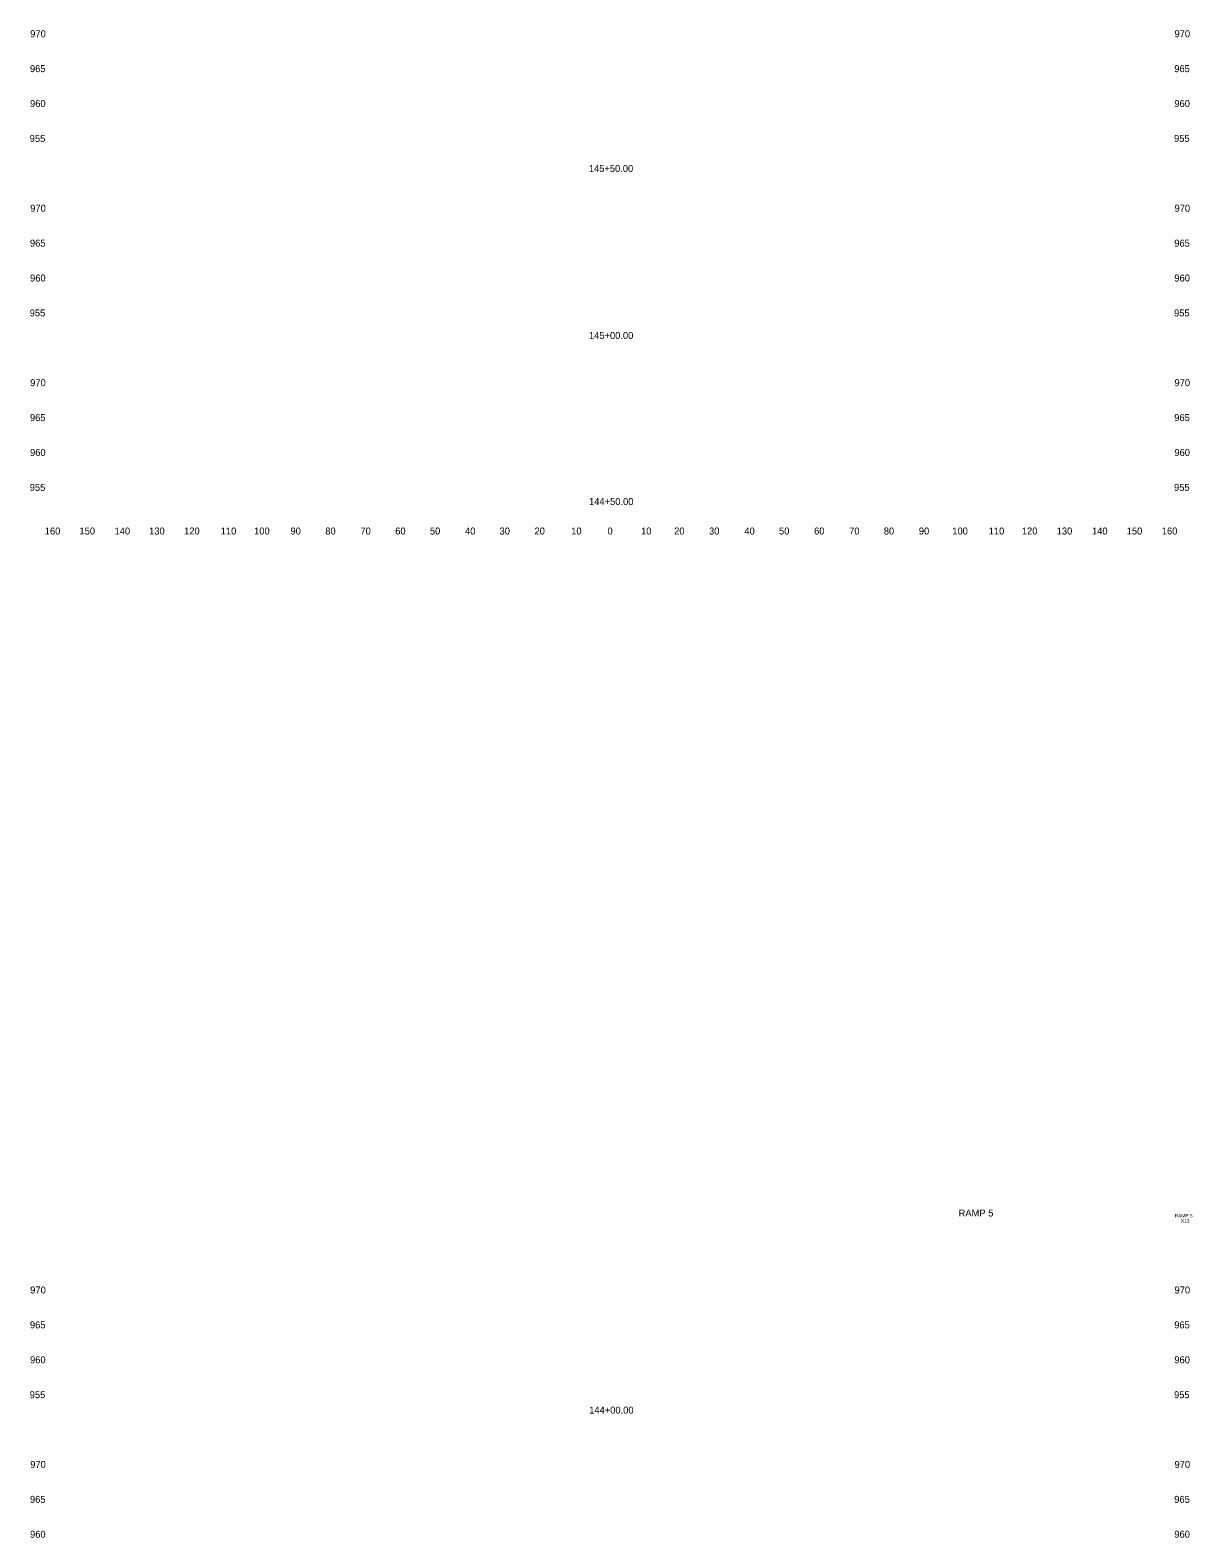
# Model space of a CAD drawing. Extents: x 4994 to 5842, y 4997 to 8804.
# Drawn here: x 5508.9 to 5841.7, y 5910 to 6342 of the extents above; entities that cross this region are included whole.
import ezdxf

# ---------------------------------------------------------------- set-up
doc = ezdxf.new("R2010")
doc.units = 0
for name, color, linetype in [('CLS_Search_Dist', 7, 'Continuous'), ('RD_XE_Ground', 7, 'Continuous'), ('UC_PD_Text', 7, 'Continuous')]:
    doc.layers.add(name, color=color, linetype=linetype)

msp = doc.modelspace()

# ---------------------------------------------------------------- texts
at = {"layer": 'CLS_Search_Dist'}
for s, p in [('970', (5508.94, 6340)), ('970', (5836.74, 6340)), ('965', (5508.86, 6330)), ('965', (5836.66, 6330)), ('960', (5508.89, 6320)), ('960', (5836.69, 6320)), ('955', (5508.8, 6310)), ('955', (5836.6, 6310)), ('970', (5508.94, 6290)), ('970', (5836.74, 6290)), ('965', (5508.86, 6280)), ('965', (5836.66, 6280)), ('960', (5508.89, 6270)), ('960', (5836.69, 6270)), ('955', (5508.8, 6260)), ('955', (5836.6, 6260)), ('970', (5508.94, 6240)), ('970', (5836.74, 6240)), ('965', (5508.86, 6230)), ('965', (5836.66, 6230)), ('960', (5508.89, 6220)), ('960', (5836.69, 6220)), ('955', (5508.8, 6210)), ('955', (5836.6, 6210)), ('160', (5513.1, 6197.5)), ('150', (5523.04, 6197.5)), ('140', (5533.1, 6197.5)), ('130', (5542.99, 6197.5)), ('120', (5553.01, 6197.5)), ('110', (5563.51, 6197.5)), ('100', (5573.07, 6197.5)), ('90', (5583.5, 6197.5)), ('80', (5593.46, 6197.5)), ('70', (5603.54, 6197.5)), ('60', (5613.5, 6197.5)), ('50', (5623.43, 6197.5)), ('40', (5633.5, 6197.5)), ('30', (5643.39, 6197.5)), ('20', (5653.4, 6197.5)), ('10', (5663.91, 6197.5)), ('0', (5674.3, 6197.5)), ('0', (5674.3, 6197.5)), ('10', (5683.91, 6197.5)), ('20', (5693.4, 6197.5)), ('30', (5703.39, 6197.5)), ('40', (5713.5, 6197.5)), ('50', (5723.43, 6197.5)), ('60', (5733.5, 6197.5)), ('70', (5743.54, 6197.5)), ('80', (5753.46, 6197.5)), ('90', (5763.5, 6197.5)), ('100', (5773.07, 6197.5)), ('110', (5783.51, 6197.5)), ('120', (5793.01, 6197.5)), ('130', (5802.99, 6197.5)), ('140', (5813.1, 6197.5)), ('150', (5823.04, 6197.5)), ('160', (5833.1, 6197.5)), ('970', (5508.94, 5980)), ('970', (5836.74, 5980)), ('965', (5508.86, 5970)), ('965', (5836.66, 5970)), ('960', (5508.89, 5960)), ('960', (5836.69, 5960)), ('955', (5508.8, 5950)), ('955', (5836.6, 5950)), ('970', (5508.94, 5930)), ('970', (5836.74, 5930)), ('965', (5508.86, 5920)), ('965', (5836.66, 5920)), ('960', (5508.89, 5910)), ('960', (5836.69, 5910))]:
    msp.add_text(s, height=2, dxfattribs=at).set_placement(p)
at = {"layer": 'RD_XE_Ground'}
for s, p in [('145+50.00', (5668.96, 6301.39)), ('145+00.00', (5668.99, 6253.54)), ('144+50.00', (5669.02, 6205.95)), ('144+00.00', (5669.06, 5945.59))]:
    msp.add_text(s, height=2, dxfattribs=at).set_placement(p)
at = {"layer": 'UC_PD_Text'}
for s, height, p in [('RAMP 5', 2, (5774.89, 6002.06)), ('RAMP 5', 1, (5836.78, 6001.8)), ('X13', 1, (5838.57, 6000.3))]:
    msp.add_text(s, height=height, dxfattribs=at).set_placement(p)

doc.saveas('drawing.dxf')
